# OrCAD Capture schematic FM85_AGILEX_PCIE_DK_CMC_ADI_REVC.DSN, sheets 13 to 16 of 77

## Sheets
13 FPGA BANK 2E: size B
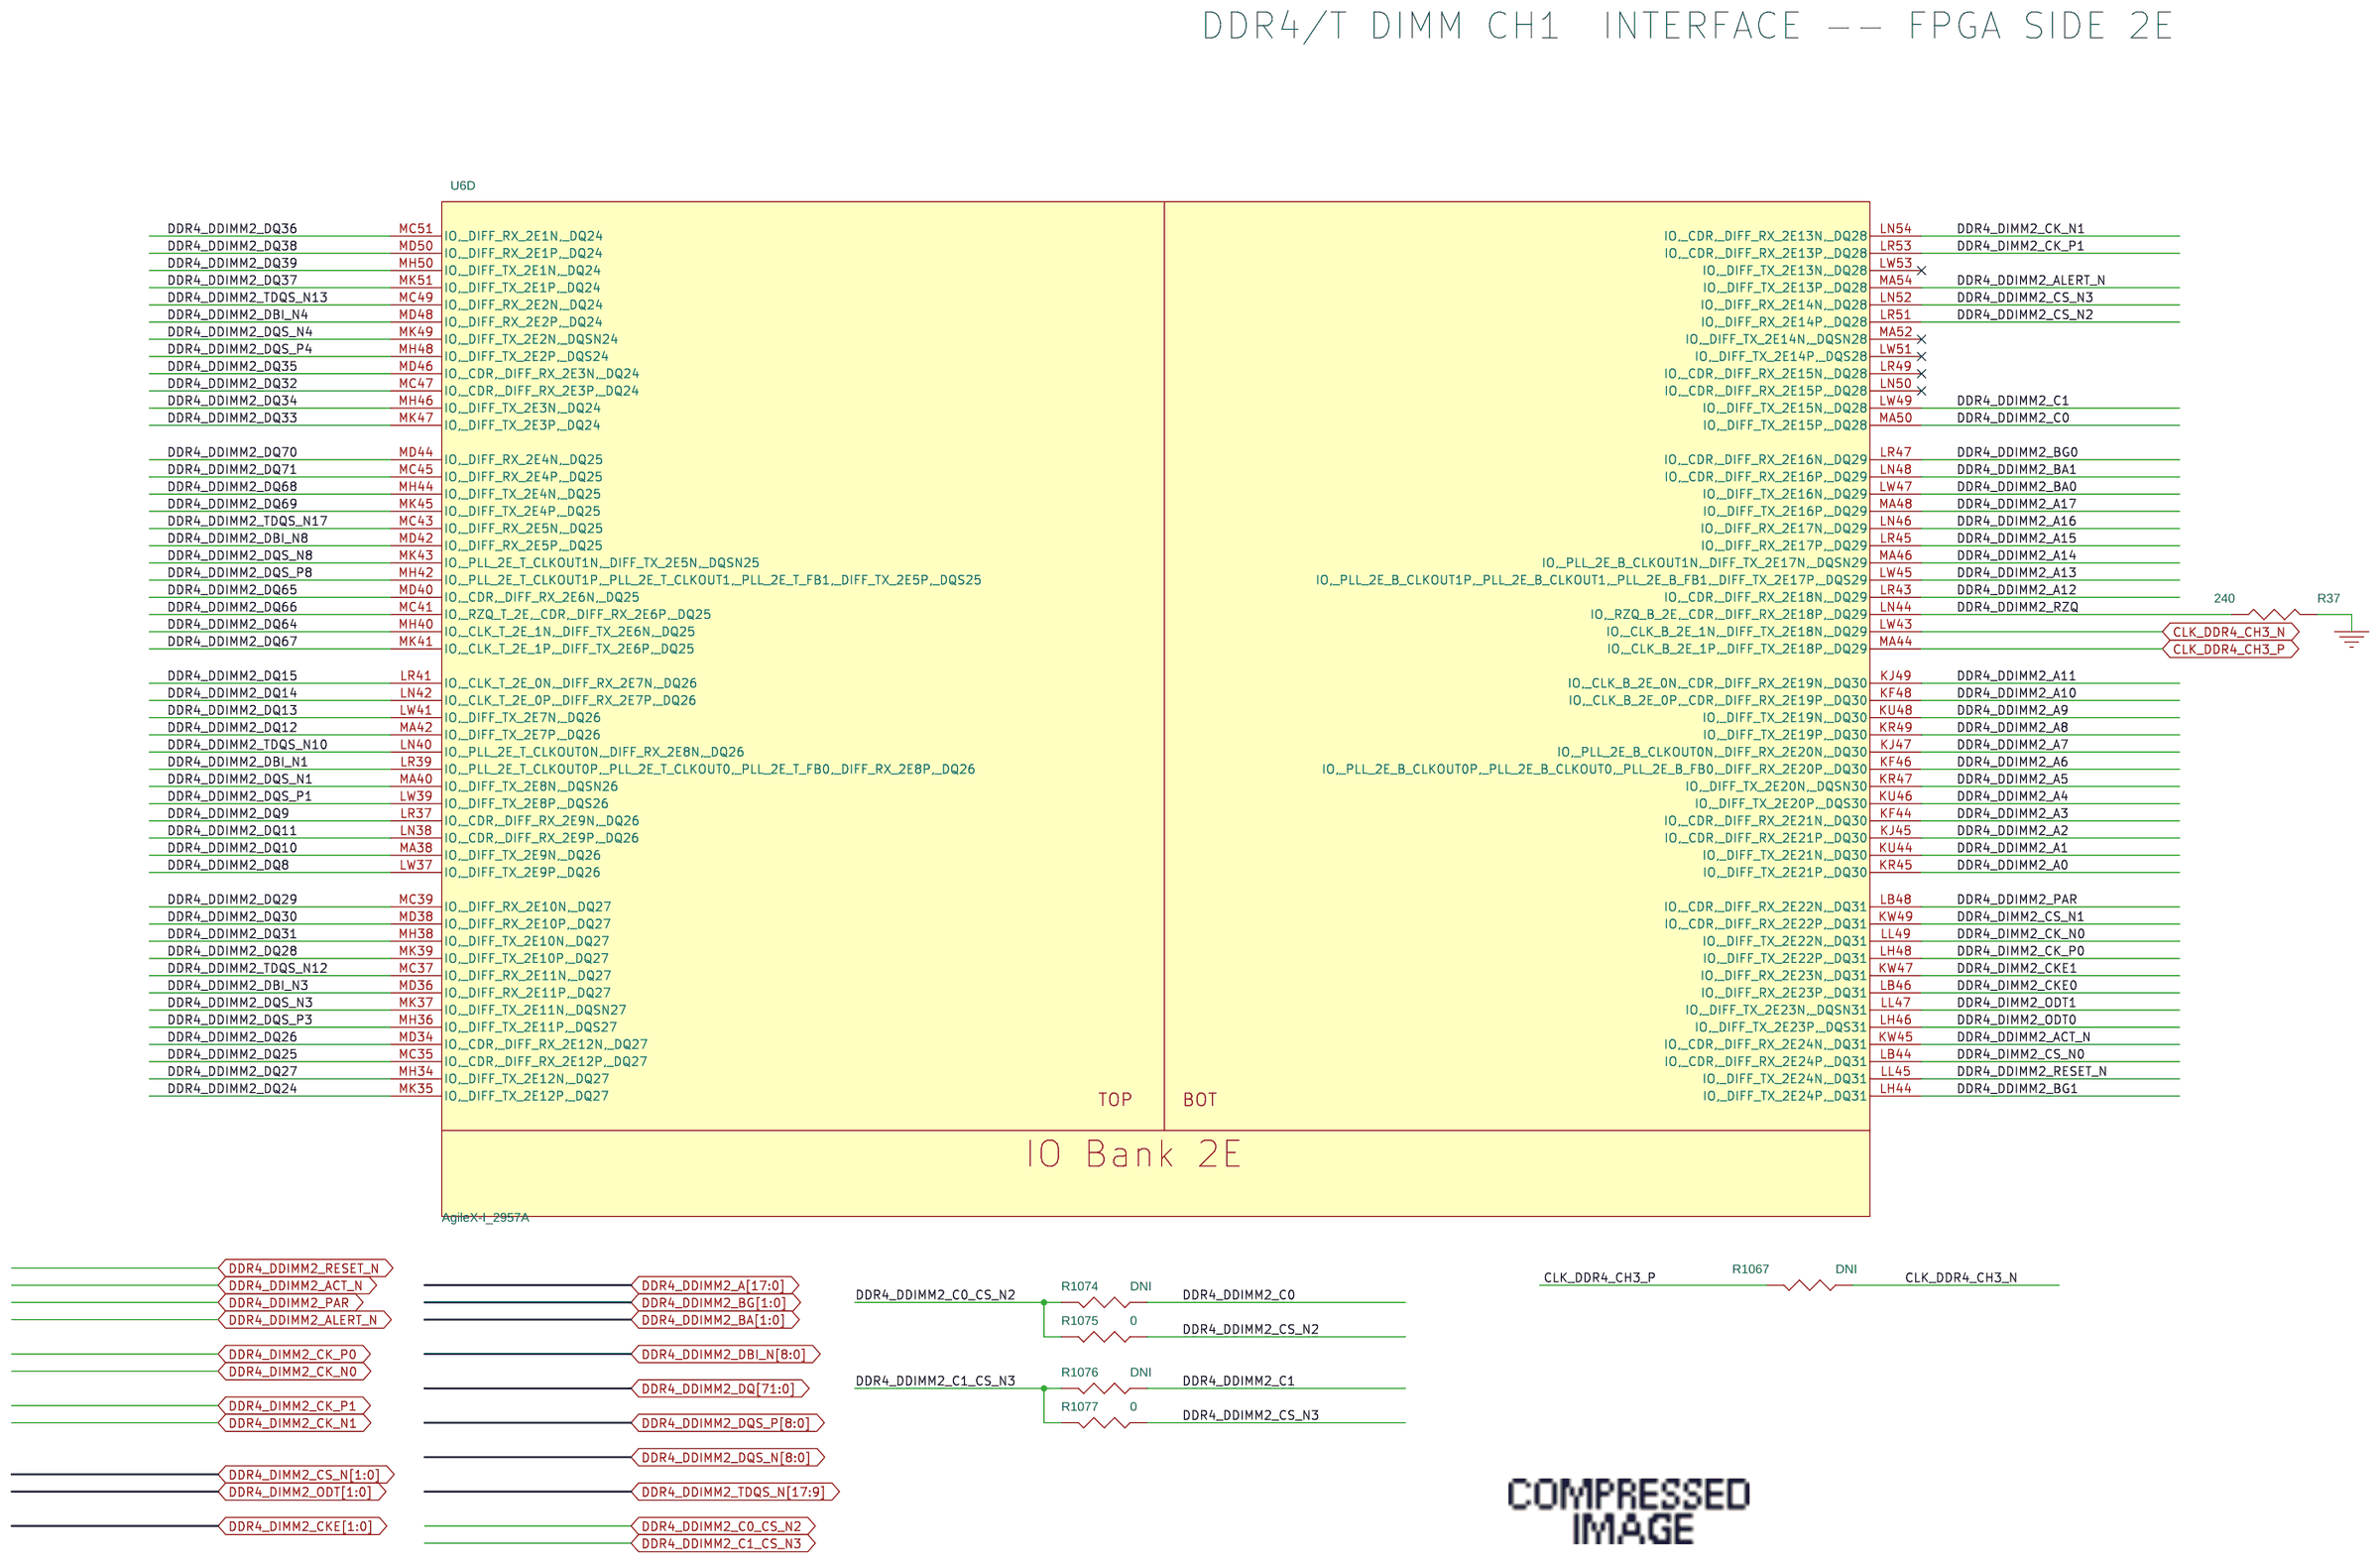
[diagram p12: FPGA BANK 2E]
14 DDR4 CH1 Component 1: size B
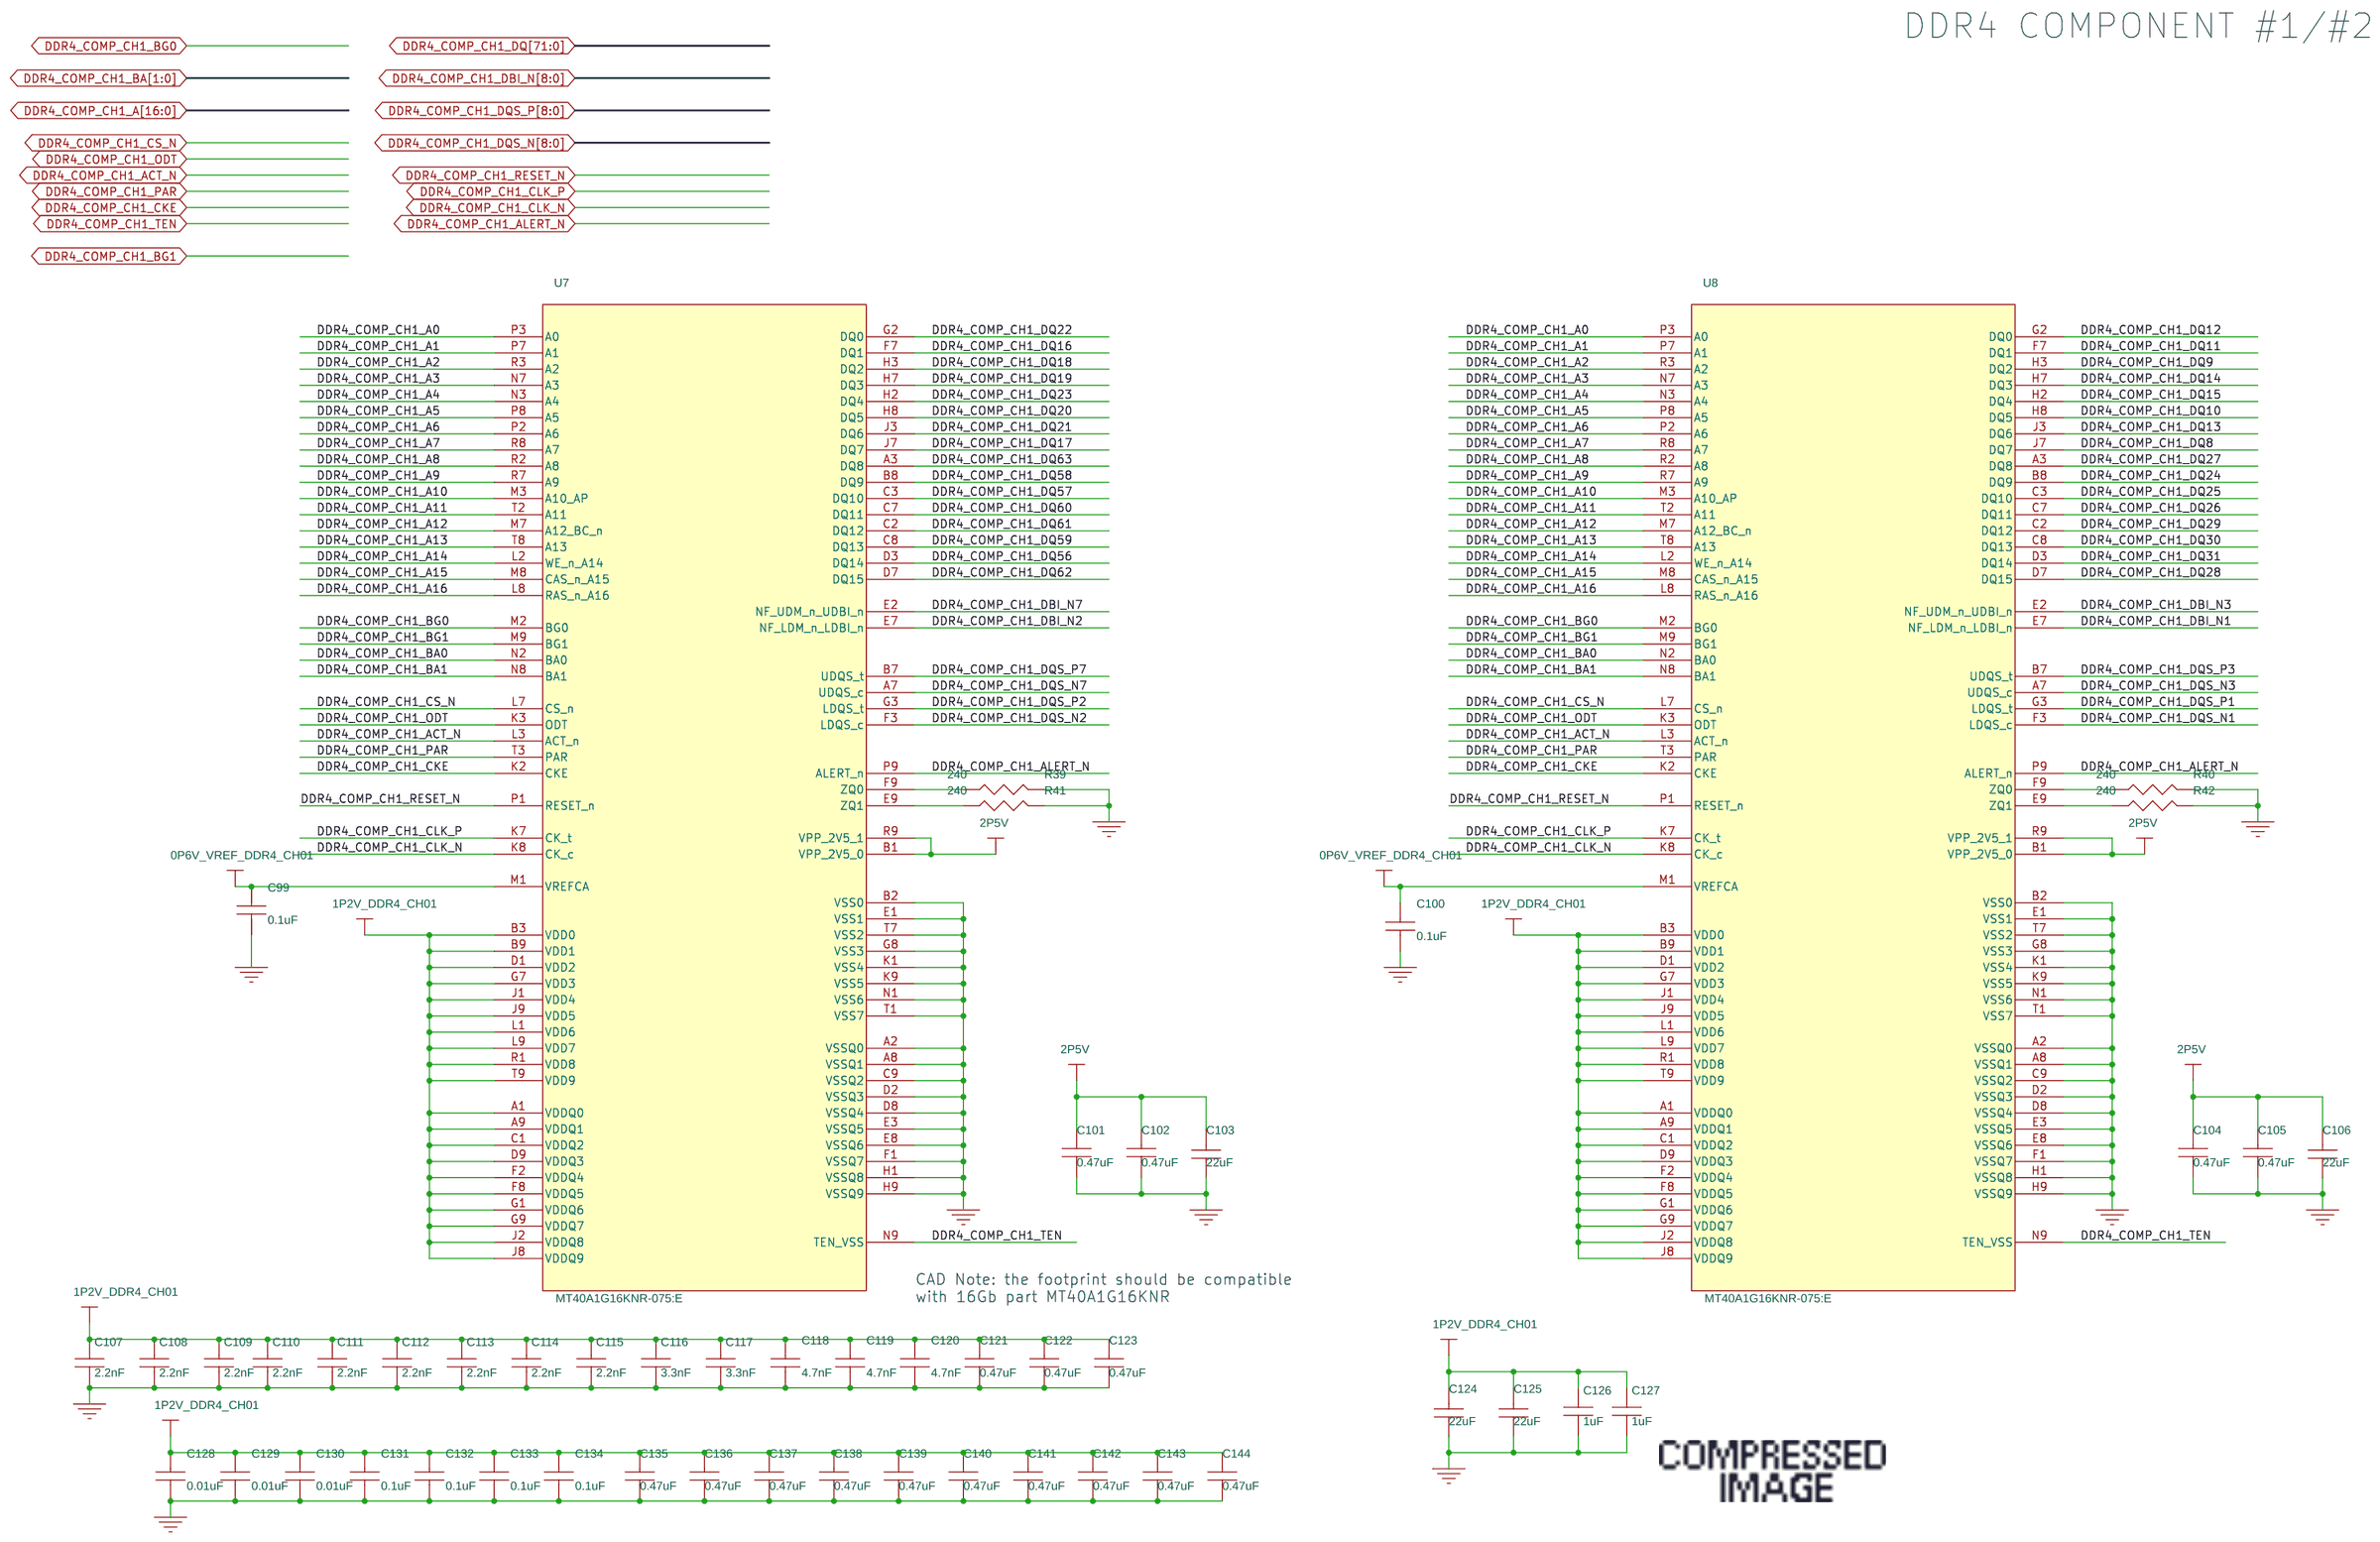
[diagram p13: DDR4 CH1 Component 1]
15 DDR4 CH1 Component 2: size B
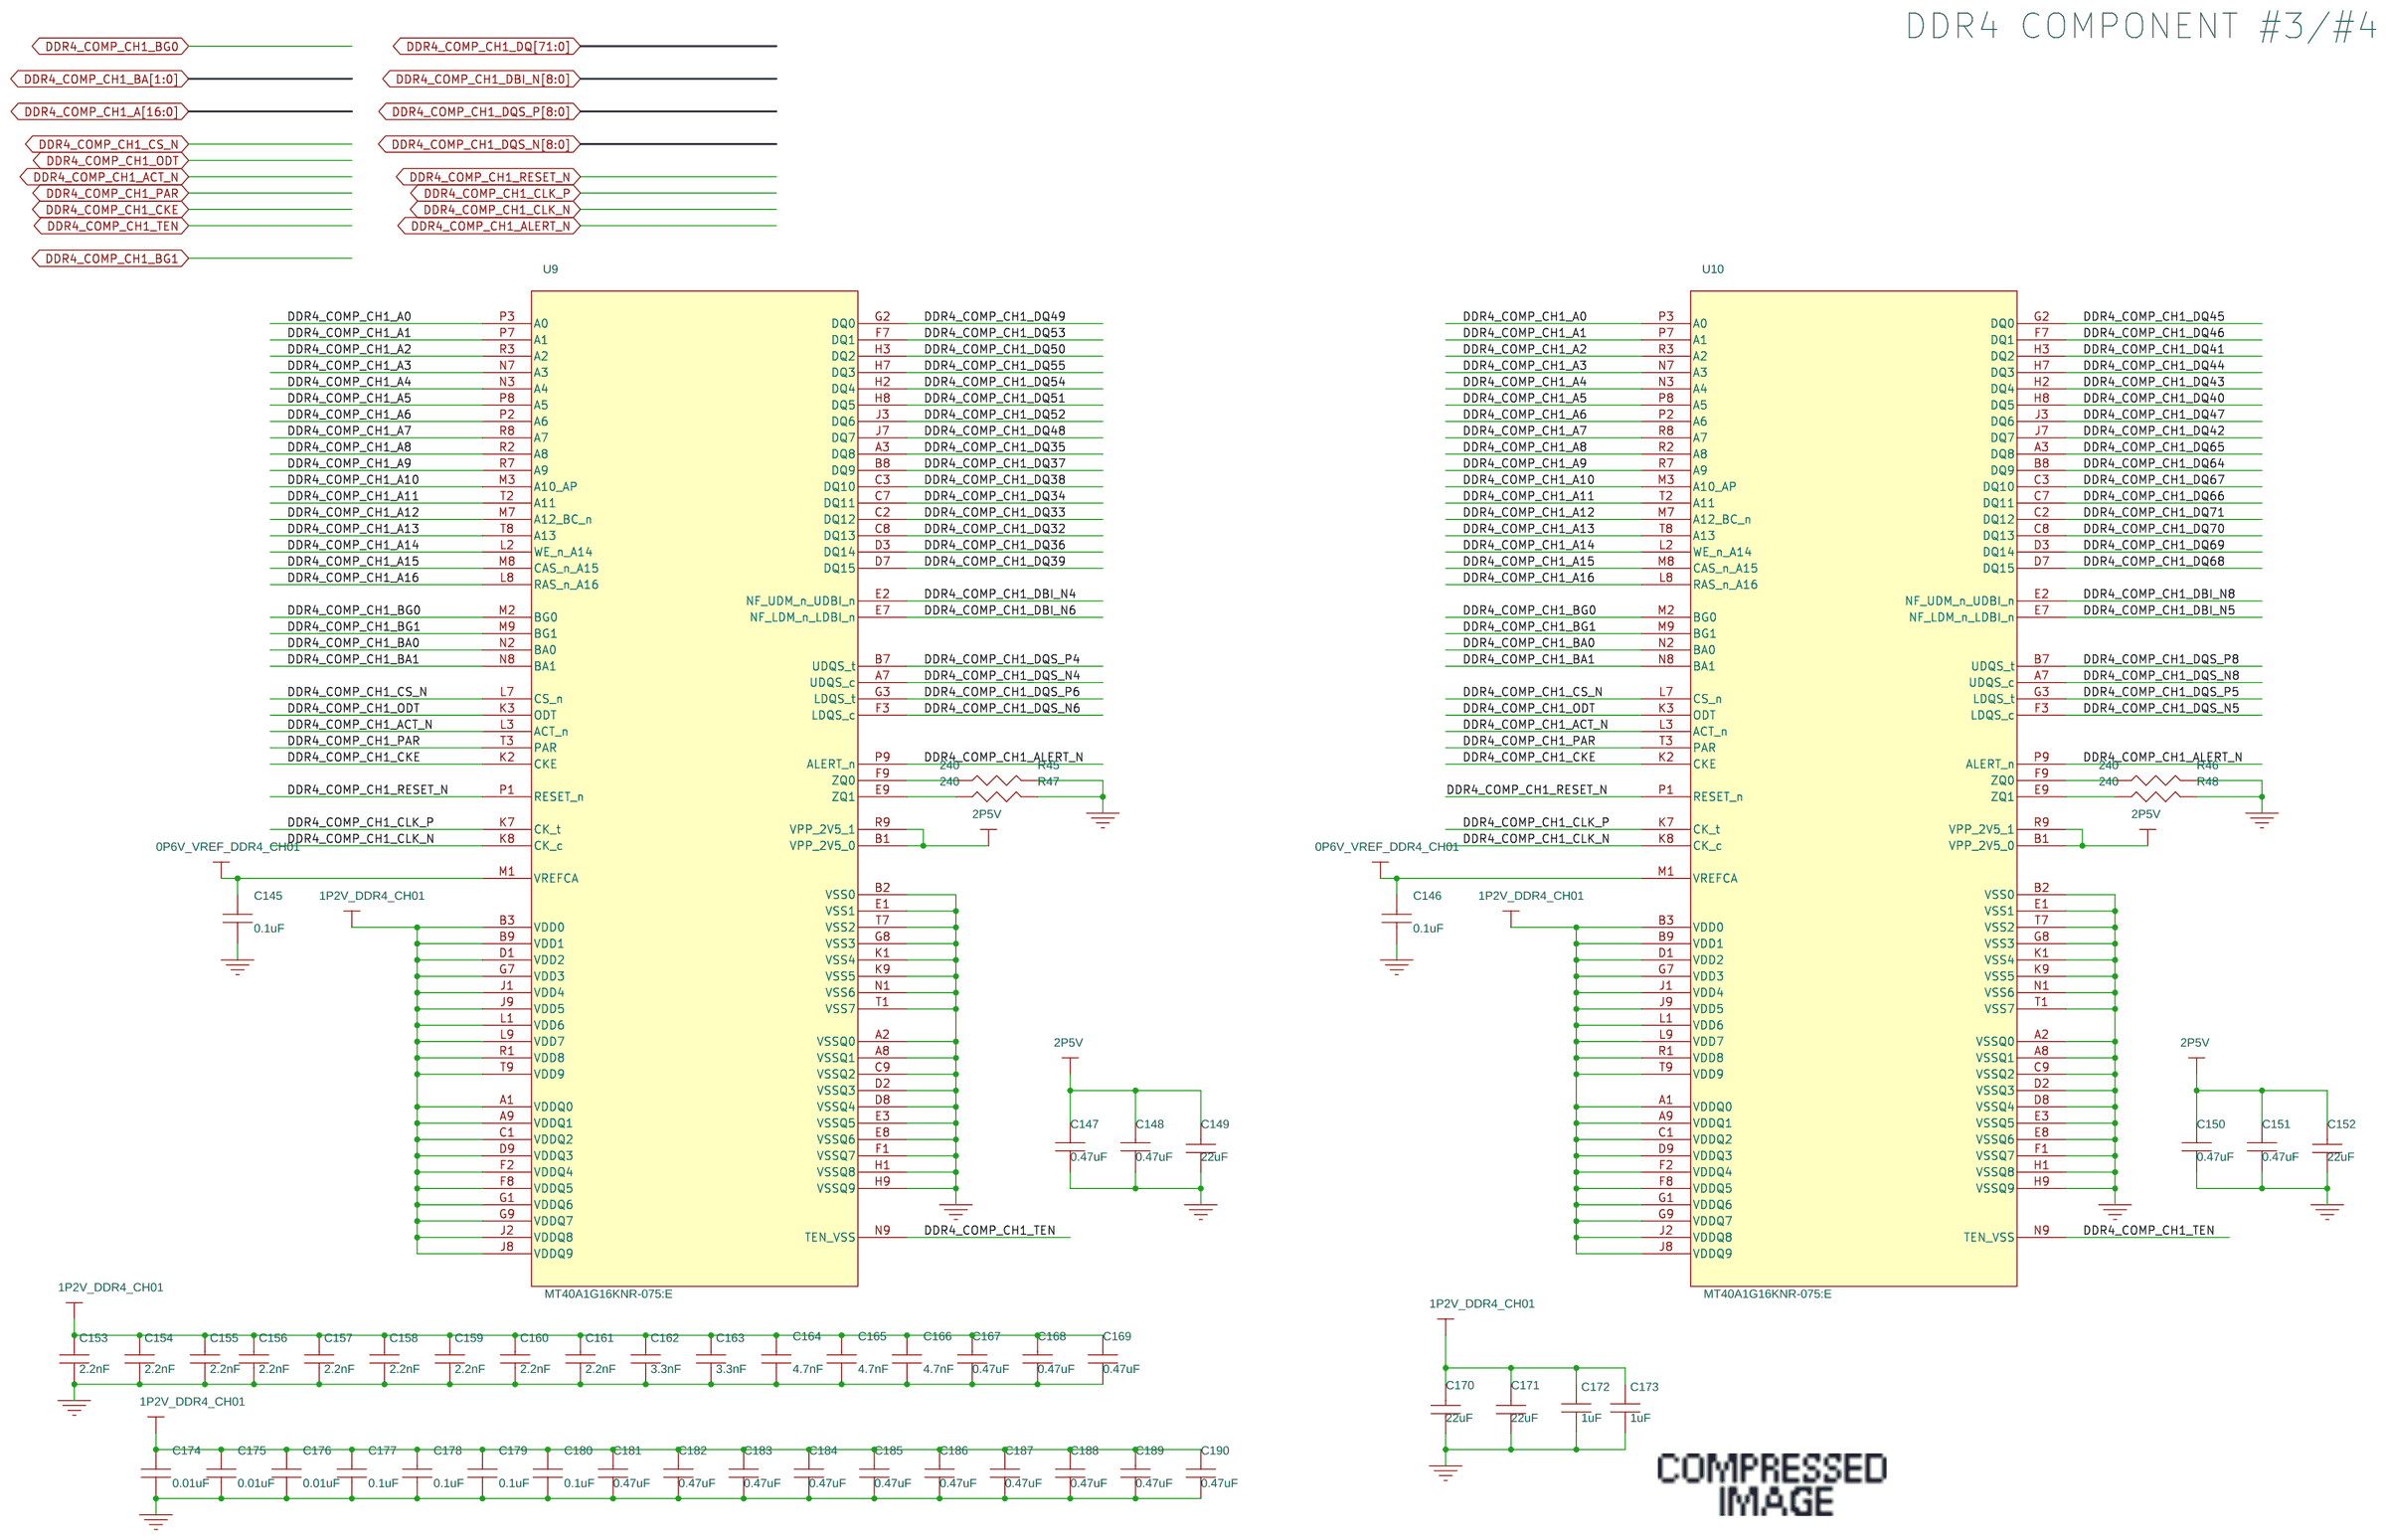
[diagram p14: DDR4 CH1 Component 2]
16 DDR4 CH1 Comp Termination: size B
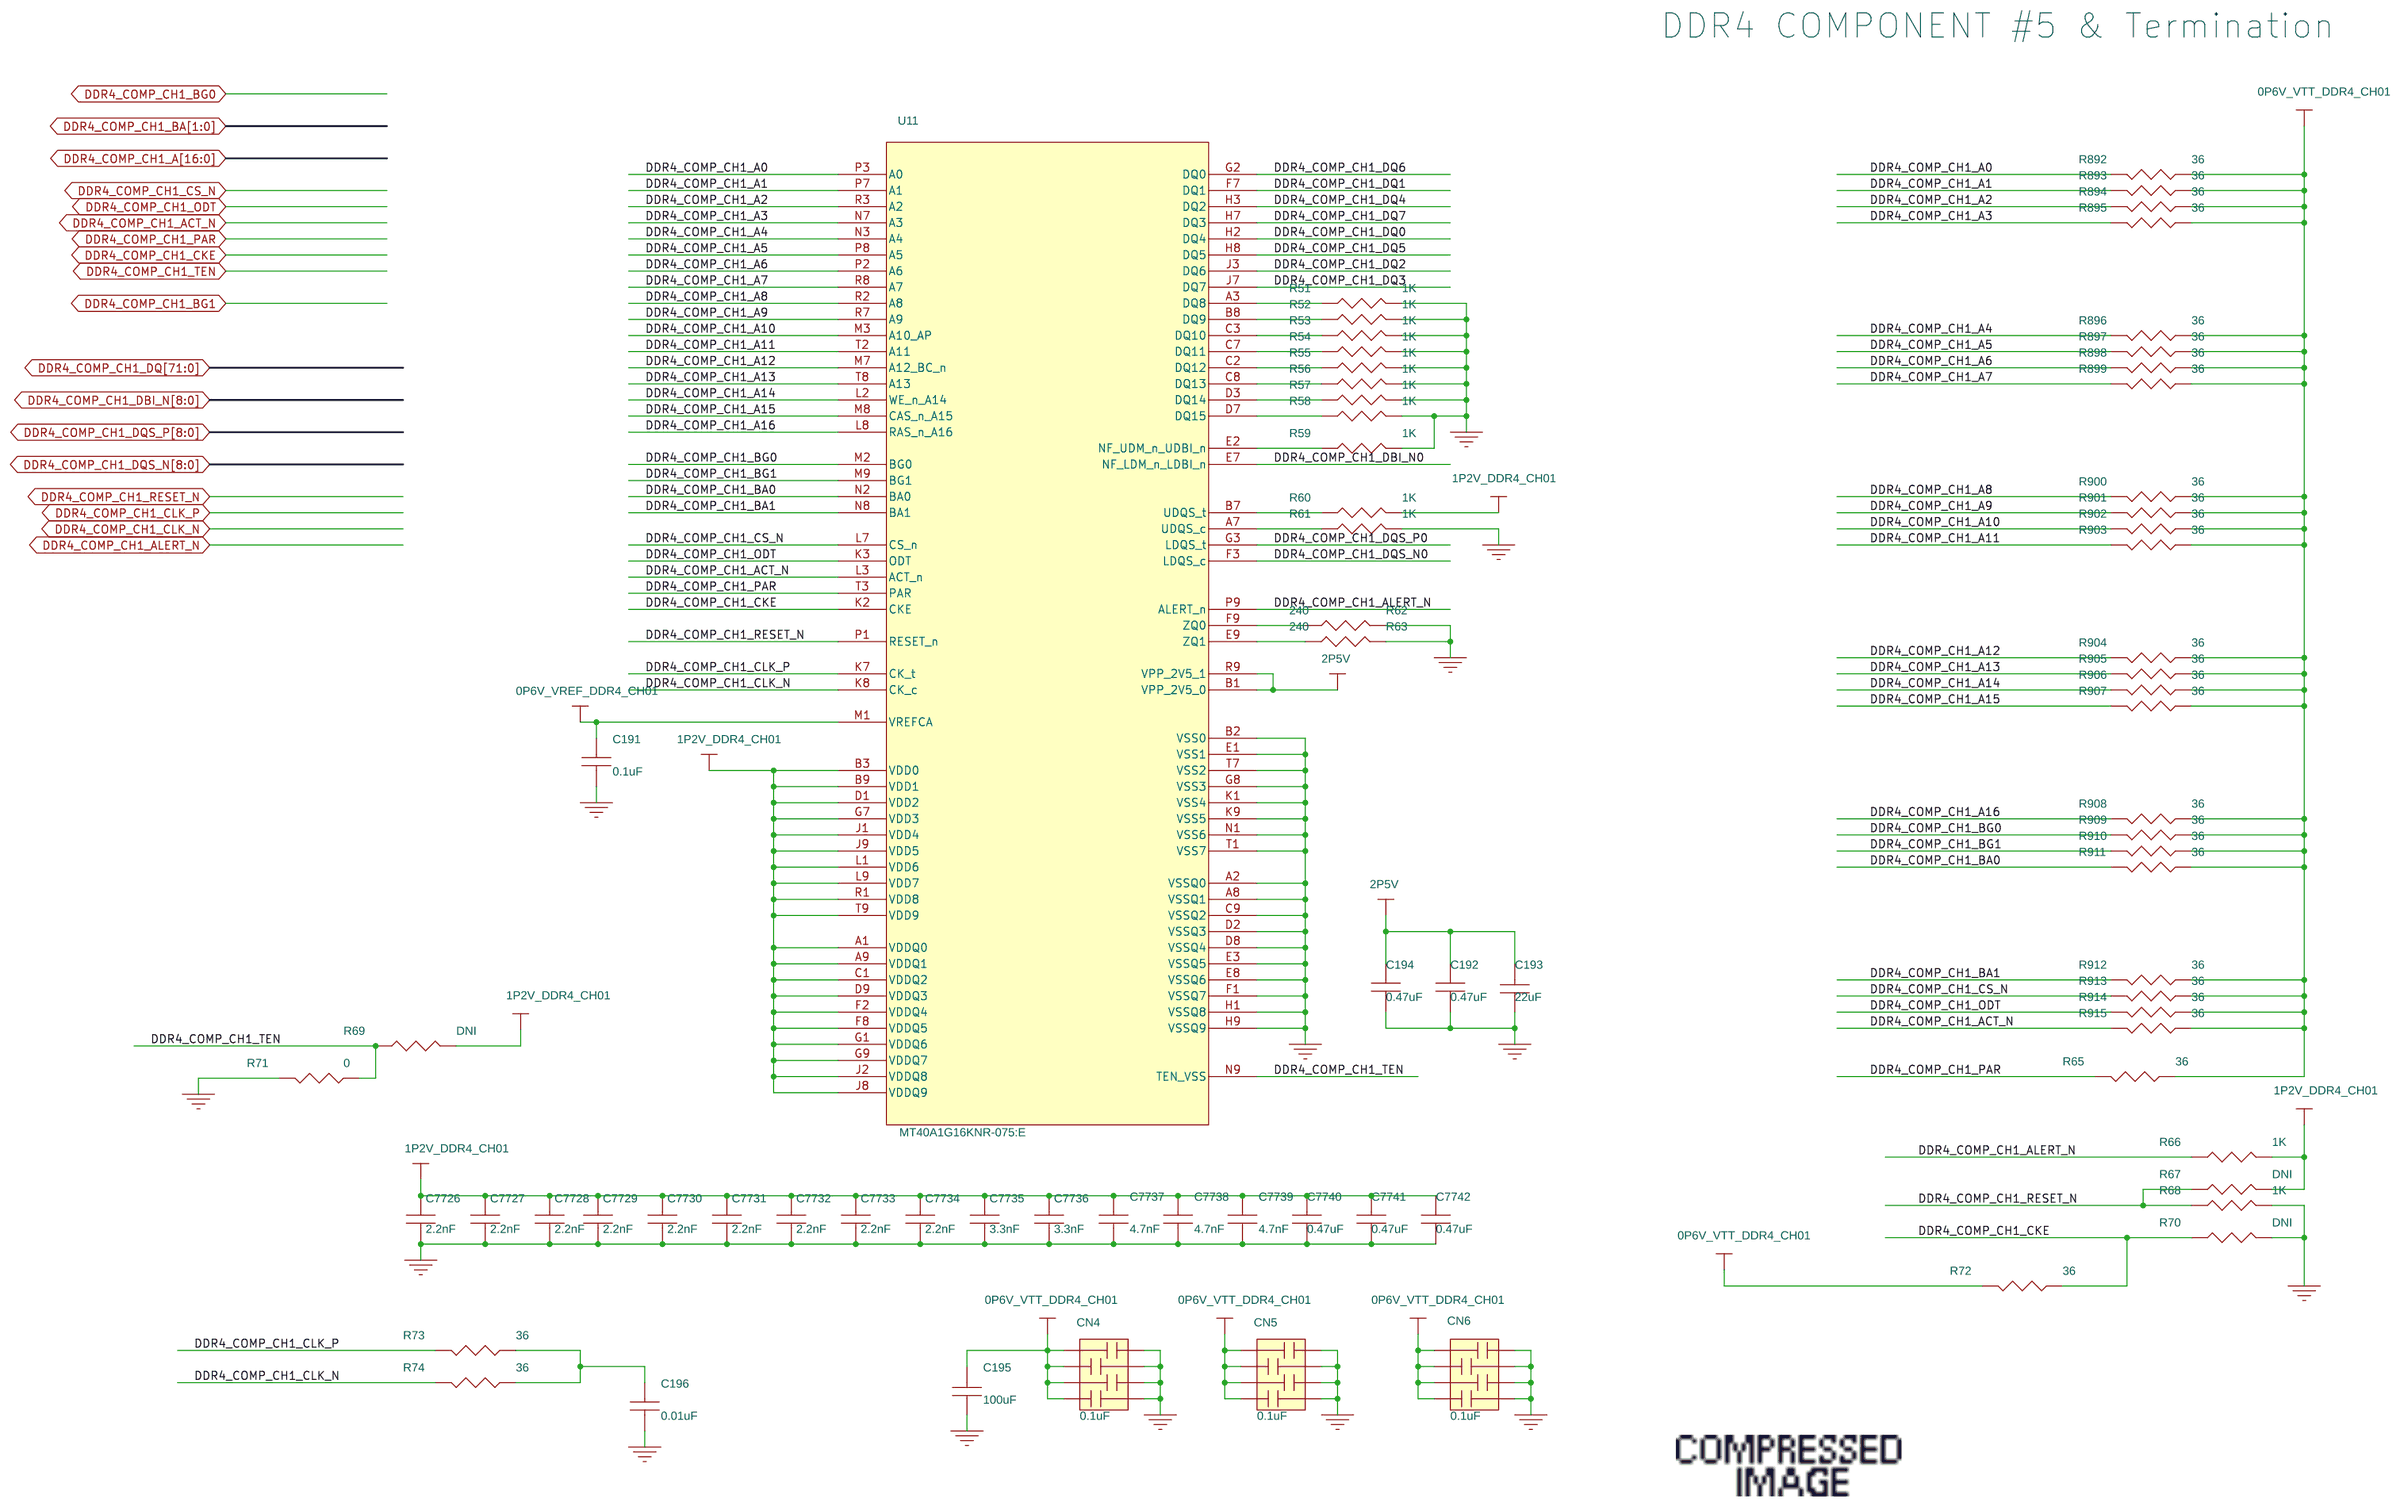
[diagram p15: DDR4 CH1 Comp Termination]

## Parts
sheet DDR4 CH1 Comp Termination
C191  0.1uF  [0402]
C192  0.47uF  [0402]
C193  22uF  [0603]
C194  0.47uF  [0402]
C195  100uF  [1206]
C196  0.01uF  [0402]
C7726  2.2nF  [0402]
C7727  2.2nF  [0402]
C7728  2.2nF  [0402]
C7729  2.2nF  [0402]
C7730  2.2nF  [0402]
C7731  2.2nF  [0402]
C7732  2.2nF  [0402]
C7733  2.2nF  [0402]
C7734  2.2nF  [0402]
C7735  3.3nF  [0402]
C7736  3.3nF  [0402]
C7737  4.7nF  [0402]
C7738  4.7nF  [0402]
C7739  4.7nF  [0402]
C7740  0.47uF  [0402]
C7741  0.47uF  [0402]
C7742  0.47uF  [0402]
CN4  0.1uF  [CAP_PACK_4_1206]
CN5  0.1uF  [CAP_PACK_4_1206]
CN6  0.1uF  [CAP_PACK_4_1206]
R51  1K  [0402]
R52  1K  [0402]
R53  1K  [0402]
R54  1K  [0402]
R55  1K  [0402]
R56  1K  [0402]
R57  1K  [0402]
R58  1K  [0402]
R59  1K  [0402]
R60  1K  [0402]
R61  1K  [0402]
R62  240  [0402]
R63  240  [0402]
R65  36  [0402]
R66  1K  [0402]
R67  DNI  [0402]
R68  1K  [0402]
R69  DNI  [0402]
R70  DNI  [0402]
R71  0  [0402]
R72  36  [0402]
R73  36  [0402]
R74  36  [0402]
R892  36  [0402]
R893  36  [0402]
R894  36  [0402]
R895  36  [0402]
R896  36  [0402]
R897  36  [0402]
R898  36  [0402]
R899  36  [0402]
R900  36  [0402]
R901  36  [0402]
R902  36  [0402]
R903  36  [0402]
R904  36  [0402]
R905  36  [0402]
R906  36  [0402]
R907  36  [0402]
R908  36  [0402]
R909  36  [0402]
R910  36  [0402]
R911  36  [0402]
R912  36  [0402]
R913  36  [0402]
R914  36  [0402]
R915  36  [0402]
U11  MT40A1G16KNR-075:E  [FBGA96]
sheet DDR4 CH1 Component 1
C99  0.1uF  [0402]
C100  0.1uF  [0402]
C101  0.47uF  [0402]
C102  0.47uF  [0402]
C103  22uF  [0603]
C104  0.47uF  [0402]
C105  0.47uF  [0402]
C106  22uF  [0603]
C107  2.2nF  [0402]
C108  2.2nF  [0402]
C109  2.2nF  [0402]
C110  2.2nF  [0402]
C111  2.2nF  [0402]
C112  2.2nF  [0402]
C113  2.2nF  [0402]
C114  2.2nF  [0402]
C115  2.2nF  [0402]
C116  3.3nF  [0402]
C117  3.3nF  [0402]
C118  4.7nF  [0402]
C119  4.7nF  [0402]
C120  4.7nF  [0402]
C121  0.47uF  [0402]
C122  0.47uF  [0402]
C123  0.47uF  [0402]
C124  22uF  [0603]
C125  22uF  [0603]
C126  1uF  [0402]
C127  1uF  [0402]
C128  0.01uF  [0402]
C129  0.01uF  [0402]
C130  0.01uF  [0402]
C131  0.1uF  [0402]
C132  0.1uF  [0402]
C133  0.1uF  [0402]
C134  0.1uF  [0402]
C135  0.47uF  [0402]
C136  0.47uF  [0402]
C137  0.47uF  [0402]
C138  0.47uF  [0402]
C139  0.47uF  [0402]
C140  0.47uF  [0402]
C141  0.47uF  [0402]
C142  0.47uF  [0402]
C143  0.47uF  [0402]
C144  0.47uF  [0402]
R39  240  [0402]
R40  240  [0402]
R41  240  [0402]
R42  240  [0402]
U7  MT40A1G16KNR-075:E  [FBGA96]
U8  MT40A1G16KNR-075:E  [FBGA96]
sheet DDR4 CH1 Component 2
C145  0.1uF  [0402]
C146  0.1uF  [0402]
C147  0.47uF  [0402]
C148  0.47uF  [0402]
C149  22uF  [0603]
C150  0.47uF  [0402]
C151  0.47uF  [0402]
C152  22uF  [0603]
C153  2.2nF  [0402]
C154  2.2nF  [0402]
C155  2.2nF  [0402]
C156  2.2nF  [0402]
C157  2.2nF  [0402]
C158  2.2nF  [0402]
C159  2.2nF  [0402]
C160  2.2nF  [0402]
C161  2.2nF  [0402]
C162  3.3nF  [0402]
C163  3.3nF  [0402]
C164  4.7nF  [0402]
C165  4.7nF  [0402]
C166  4.7nF  [0402]
C167  0.47uF  [0402]
C168  0.47uF  [0402]
C169  0.47uF  [0402]
C170  22uF  [0603]
C171  22uF  [0603]
C172  1uF  [0402]
C173  1uF  [0402]
C174  0.01uF  [0402]
C175  0.01uF  [0402]
C176  0.01uF  [0402]
C177  0.1uF  [0402]
C178  0.1uF  [0402]
C179  0.1uF  [0402]
C180  0.1uF  [0402]
C181  0.47uF  [0402]
C182  0.47uF  [0402]
C183  0.47uF  [0402]
C184  0.47uF  [0402]
C185  0.47uF  [0402]
C186  0.47uF  [0402]
C187  0.47uF  [0402]
C188  0.47uF  [0402]
C189  0.47uF  [0402]
C190  0.47uF  [0402]
R45  240  [0402]
R46  240  [0402]
R47  240  [0402]
R48  240  [0402]
U9  MT40A1G16KNR-075:E  [FBGA96]
U10  MT40A1G16KNR-075:E  [FBGA96]
sheet FPGA BANK 2E
R37  240  [0402]
R1067  DNI  [0402]
R1074  DNI  [0402]
R1075  0  [0402]
R1076  DNI  [0402]
R1077  0  [0402]
sheet FPGA BANK 2F
U6  AgileX-I_2957A  [fbga2957a_hex_p56x45]  (sections A,B,C,D,E,F,G,H,I,J,K,L,M,N,O,P,Q,R,S,T,U,V,W,X,Y,Z)

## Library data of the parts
C99 C100 C131-C134 C145 C146 C177 C178 C180 C191 = CAP: CAPC,  X7R, 0402, 0.1uF, 25V, ±20%; Item Num: K13660-001; LIFECYCLE_PHASE: Active; Lead Free Status: Lead Free; MFR_LIFECYCLE: Active; Manufacturer: Murata; Manufacturer Part Num: GRM155R71E104KE14D; Num Pins: 2; PART_SUBCLASS: CAPACITORS; Part Class: CAPACITORS; RATED_VOLTAGE: 25V; RoHS Compliant: RoHS Compliant; Tolerance: +80%/-20%
C101 C102 C104 C105 C121-C123 C135-C144 C147 C148 C150 C151 C167-C169 C181-C190 C192 C194 C7740-C7742 = CAP: CAP - CER, .47UF, 10V, X5R, 0402; AGILE_LINK: http://sj-agile9app/Agile/PLMServlet?action=OpenEmailObject&classid=10000&objid=256989651; Item Num: H75789-001; LIFECYCLE_PHASE: Active; Lead Free Status: Lead Free; MFR_LIFECYCLE: Active; Manufacturer: Murata; Manufacturer Part Num: GRM155R61A474KE15D; Num Pins: 2; PART_SUBCLASS: CAPACITORS; Part Class: CAPACITORS; RATED_VOLTAGE: 10V; RoHS Compliant: RoHS Compliant; Tolerance: +80%/-20%
C103 C106 C124 C125 C149 C152 C170 C171 C193 = CAP: CAP CER 22UF 6.3V X6S 0603; AGILE_LINK: http://sj-agile9app/Agile/PLMServlet?action=OpenEmailObject&classid=10000&objid=257560276; Item Num: H63299-001; LIFECYCLE_PHASE: Active; Lead Free Status: Not Lead Free; MFR_LIFECYCLE: Active; Manufacturer: Murata; Manufacturer Part Num: GRM188C80J226ME15D; Num Pins: 2; PART_SUBCLASS: CAPACITORS; RATED_VOLTAGE: 6.3V; RoHS Compliant: RoHS Compliant; TOLERANCE: 20%; Temperature Coefficient: X6S
C195 = CAP: CAP CER 100UF 6.3V X6T 1206; AGILE_LINK: http://sj-agile9app/Agile/PLMServlet?action=OpenEmailObject&classid=10000&objid=257560276; Item Num: H65271-004; LIFECYCLE_PHASE: Active; Lead Free Status: Lead Free; MFR_LIFECYCLE: Active; Manufacturer: Murata; Manufacturer Part Num: GRM31CD80J107ME39L; Num Pins: 2; PART_SUBCLASS: CAPACITORS; RATED_VOLTAGE: 6.3V; RoHS Compliant: RoHS Compliant; TOLERANCE: 20%; Temperature Coefficient: X6T
C128-C130 C174-C176 C196 = CAP: CAP, CER .01UF 16V X7R 0402; Item Num: A36096-007; Lead Free Status: No; Manufacturer: Murata; Manufacturer Part Num: GRM155R71C103KA01D; Manufacturer's Part No.: GRM155R71C103KA01D; Num Pins: 2; Part Class: CAPACITORS; Price: 0; RoHS Compliant: Yes
C7726-C7734 = CAP: CAP CER 2200PF 50V 10% X7R 0402; AGILE_LINK: http://sj-agile9app/Agile/PLMServlet?action=OpenEmailObject&classid=10000&objid=204246494; CAPACITANCE: 2200pF; Item Num: H63810-001; LIFECYCLE_PHASE: Active; Manufacturer: Murata; Manufacturer Part Num: GRM155R71H222KA01D; Num Pins: 2; PART_SUBCLASS: CAPACITORS; RATED_VOLTAGE: 50V; TOLERANCE: +/-10%
C116 C117 C162 C163 C7735 C7736 = CAP: CAP, CERAMIC, 3300PF, 10%, 50V, X7R, 0402; AGILE_LINK: http://sj-agile9app/Agile/PLMServlet?action=OpenEmailObject&classid=10000&objid=257002141; Item Num: K13754-001; LIFECYCLE_PHASE: Active; Lead Free Status: Lead Free; MFR_LIFECYCLE: Active; Manufacturer: Murata; Manufacturer Part Num: GRM155F51H332ZA01x; Num Pins: 2; PART_SUBCLASS: CAPACITORS; RATED_VOLTAGE: 50V; RoHS Compliant: RoHS Compliant; TOLERANCE: +/-10%
C118-C120 C164-C166 C7737-C7739 = CAP: CAP - CER 4700PF 50V 10% X7R 0402; AGILE_LINK: http://sj-agile9app/Agile/PLMServlet?action=OpenEmailObject&classid=10000&objid=215384813; Item Num: G24897-001; LIFECYCLE_PHASE: Active; Lead Free Status: Lead Free; MFR_LIFECYCLE: Active; Manufacturer: Murata; Manufacturer Part Num: GRM155R71H472KA01D; Num Pins: 2; PACKAGING: Tape & Reel (TR); PART_SUBCLASS: CAPACITORS; RATED_VOLTAGE: 50V; RoHS Compliant: RoHS Compliant; Supplier Part Num: GRM155R71H472KA01D; Tolerance: +/-10%
CN4-CN6 = CAP_ARRAY: CAPNET, 4 CAPS, CERAMIC, 0.1uF, 1206, 20%, 16VDC, X7R; Item Num: J41786-001; Manufacturer: Panasonic; Manufacturer Part Num: ECJ-RVB1C104M
R51-R61 R66-R70 = RESISTOR: RES,1.00K OHMS,1.0%,1/16W,0402; Item Num: G60609-021; Lead Free Status: No; Manufacturer: Panasonic; Manufacturer Part Num: ERJ-2RKF1001X; Num Pins: 2; Part Class: Resistors
R37 R39-R42 R45-R48 R62 R63 = RESISTOR: RES - 240 OHM, 1/16W, 1%, 0402 SMD; Item Num: K15783-001; LIFECYCLE_PHASE: Active; Lead Free Status: Lead Free; MFR_LIFECYCLE: Active; Manufacturer: Panasonic; Manufacturer Part Num: ERJ-2RKF2400X; Num Pins: 2; PART_SUBCLASS: RESISTORS; RoHS Compliant: RoHS Compliant
R65 R72-R74 R892-R915 = RESISTOR: RES_D,0402,36.00OHM,1.00%,1/16W,; Item Num: A93548-623; Lead Free Status: Yes; Manufacturer: VISHAY; Manufacturer Part Num: CRCW040236R0FKED; Num Pins: 2; Part Class: Resistors; Price: 0
R71 R1074-R1077 = RES_0_OHM_5%_1_16W_0402_SMD: Item Num: H30887-001
U7-U11 = MT40A1G16HBA-083E_0: IC - Memory, 64M x 16 x 16 Banks x 1 Rank, 1.2V DDR4 SDRAM, TwinDie; Item Num: K20740-001; Manufacturer: Micron
C107-C115 C153-C161 = CAP: CAP CER 2200PF 50V 10% X7R 0402; AGILE_LINK: http://sj-agile9app/Agile/PLMServlet?action=OpenEmailObject&classid=10000&objid=204246494; CAPACITANCE: 2200pF; Item Num: A36096-022; LIFECYCLE_PHASE: Active; Manufacturer: Murata; Manufacturer Part Num: GRM155R71H222KA01D; Num Pins: 2; PART_SUBCLASS: CAPACITORS; RATED_VOLTAGE: 50V; TOLERANCE: +/-10%
C126 C127 C172 C173 = CAP: CAP - CER, 1uF, 10V, +/-10%, X5R, 0402; Item Num: G61001-001; Lead Free Status: Yes; Manufacturer: Murata; Manufacturer Part Num: GRM155R61A105KE15D; Num Pins: 2; Part Class: CAPACITORS; RoHS Compliant: Yes
C179 = CAP: CAPC,  X7R, 0402, 0.1uF, 25V, ±20%; Dielectric: Y5V; Item Num: K13660-001; LIFECYCLE_PHASE: Active; Lead Free Status: Lead Free; MFR_LIFECYCLE: Active; Manufacturer: Murata; Manufacturer Part Num: GRM155R71E104KE14D; Num Pins: 2; PART_SUBCLASS: CAPACITORS; Part Class: CAPACITORS; RATED_VOLTAGE: 25V; RoHS Compliant: RoHS Compliant; Tolerance: +80%/-20%
R1067 = RESISTOR: RES,100 OHMS,1.0%,1/16W,0402; Item Num: A36092-043; Lead Free Status: No; Manufacturer: Panasonic; Manufacturer Part Num: ERJ-2RKF1000X; Manufacturer's Part No.: ERJ-2RKF1000X; Num Pins: 2; Part Class: RESISTORS; Price: 0; RoHS Compliant: Yes
U6 = AgileX-I_2957A: Item Num: 99C7VA

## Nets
GND: C99.2 C100.2 C101.2 C102.2 C103.1 C104.2 C105.2 C106.1 C107.2 C108.2 C109.2 C110.2 C111.2 C112.2 C113.2 C114.2 C115.2 C116.2 C117.2 C118.2 C119.2 C120.2 C121.2 C122.2 C123.2 C124.1 C125.1 C126.2 C127.2 C128.2 C129.2 C130.2 C131.2 C132.2 C133.2 C134.2 C135.2 C136.2 C137.2 C138.2 C139.2 C140.2 C141.2 C142.2 C143.2 C144.2 C145.2 C146.2 C147.2 C148.2 C149.1 C150.2 C151.2 C152.1 C153.2 C154.2 C155.2 C156.2 C157.2 C158.2 C159.2 C160.2 C161.2 C162.2 C163.2 C164.2 C165.2 C166.2 C167.2 C168.2 C169.2 C170.1 C171.1 C172.2 C173.2 C174.2 C175.2 C176.2 C177.2 C178.2 C179.2 C180.2 C181.2 C182.2 C183.2 C184.2 C185.2 C186.2 C187.2 C188.2 C189.2 C190.2 C191.2 C192.2 C193.1 C194.2 C195.1 C196.2 C7726.2 C7727.2 C7728.2 C7729.2 C7730.2 C7731.2 C7732.2 C7733.2 C7734.2 C7735.2 C7736.2 C7737.2 C7738.2 C7739.2 C7740.2 C7741.2 C7742.2 CN4.5 CN4.6 CN4.7 CN4.8 CN5.5 CN5.6 CN5.7 CN5.8 CN6.5 CN6.6 CN6.7 CN6.8 R37.2 R39.2 R40.2 R41.2 R42.2 R45.2 R46.2 R47.2 R48.2 R51.1 R52.1 R53.1 R54.1 R55.1 R56.1 R57.1 R58.1 R59.1 R61.1 R62.2 R63.2 R68.1 R70.1 R71.2 U7.A2(VSSQ0) U7.A8(VSSQ1) U7.B2(VSS0) U7.C9(VSSQ2) U7.D2(VSSQ3) U7.D8(VSSQ4) U7.E1(VSS1) U7.E3(VSSQ5) U7.E8(VSSQ6) U7.F1(VSSQ7) U7.G8(VSS3) U7.H1(VSSQ8) U7.H9(VSSQ9) U7.K1(VSS4) U7.K9(VSS5) U7.N1(VSS6) U7.T1(VSS7) U7.T7(VSS2) U8.A2(VSSQ0) U8.A8(VSSQ1) U8.B2(VSS0) U8.C9(VSSQ2) U8.D2(VSSQ3) U8.D8(VSSQ4) U8.E1(VSS1) U8.E3(VSSQ5) U8.E8(VSSQ6) U8.F1(VSSQ7) U8.G8(VSS3) U8.H1(VSSQ8) U8.H9(VSSQ9) U8.K1(VSS4) U8.K9(VSS5) U8.N1(VSS6) U8.T1(VSS7) U8.T7(VSS2) U9.A2(VSSQ0) U9.A8(VSSQ1) U9.B2(VSS0) U9.C9(VSSQ2) U9.D2(VSSQ3) U9.D8(VSSQ4) U9.E1(VSS1) U9.E3(VSSQ5) U9.E8(VSSQ6) U9.F1(VSSQ7) U9.G8(VSS3) U9.H1(VSSQ8) U9.H9(VSSQ9) U9.K1(VSS4) U9.K9(VSS5) U9.N1(VSS6) U9.T1(VSS7) U9.T7(VSS2) U10.A2(VSSQ0) U10.A8(VSSQ1) U10.B2(VSS0) U10.C9(VSSQ2) U10.D2(VSSQ3) U10.D8(VSSQ4) U10.E1(VSS1) U10.E3(VSSQ5) U10.E8(VSSQ6) U10.F1(VSSQ7) U10.G8(VSS3) U10.H1(VSSQ8) U10.H9(VSSQ9) U10.K1(VSS4) U10.K9(VSS5) U10.N1(VSS6) U10.T1(VSS7) U10.T7(VSS2) U11.A2(VSSQ0) U11.A8(VSSQ1) U11.B2(VSS0) U11.C9(VSSQ2) U11.D2(VSSQ3) U11.D8(VSSQ4) U11.E1(VSS1) U11.E3(VSSQ5) U11.E8(VSSQ6) U11.F1(VSSQ7) U11.G8(VSS3) U11.H1(VSSQ8) U11.H9(VSSQ9) U11.K1(VSS4) U11.K9(VSS5) U11.N1(VSS6) U11.T1(VSS7) U11.T7(VSS2) ; also on sheet 9 10 11 17 18 19 20 21 22 23 25 26 27 28 29 30 31 32 33 34 35 36 38 39 40 41 42 43 44 45 46 47 48 49 50 51 52 53 54 55 56 57 58 59 60 61 62 63 64 65 66 67 68 69 70 71 72 73 74 75 76 77
0p6V_VREF_DDR4_CH01: C99.1 C100.1 C145.1 C146.1 C191.1 U7.M1(VREFCA) U8.M1(VREFCA) U9.M1(VREFCA) U10.M1(VREFCA) U11.M1(VREFCA) ; also on sheet 9 10 11 39 72 76
0p6V_VTT_DDR4_CH01: C195.2 CN4.1 CN4.2 CN4.3 CN4.4 CN5.1 CN5.2 CN5.3 CN5.4 CN6.1 CN6.2 CN6.3 CN6.4 R65.1 R72.2 R892.1 R893.1 R894.1 R895.1 R896.1 R897.1 R898.1 R899.1 R900.1 R901.1 R902.1 R903.1 R904.1 R905.1 R906.1 R907.1 R908.1 R909.1 R910.1 R911.1 R912.1 R913.1 R914.1 R915.1 ; also on sheet 11 72
1p2V_DDR4_CH01: C107.1 C108.1 C109.1 C110.1 C111.1 C112.1 C113.1 C114.1 C115.1 C116.1 C117.1 C118.1 C119.1 C120.1 C121.1 C122.1 C123.1 C124.2 C125.2 C126.1 C127.1 C128.1 C129.1 C130.1 C131.1 C132.1 C133.1 C134.1 C135.1 C136.1 C137.1 C138.1 C139.1 C140.1 C141.1 C142.1 C143.1 C144.1 C153.1 C154.1 C155.1 C156.1 C157.1 C158.1 C159.1 C160.1 C161.1 C162.1 C163.1 C164.1 C165.1 C166.1 C167.1 C168.1 C169.1 C170.2 C171.2 C172.1 C173.1 C174.1 C175.1 C176.1 C177.1 C178.1 C179.1 C180.1 C181.1 C182.1 C183.1 C184.1 C185.1 C186.1 C187.1 C188.1 C189.1 C190.1 C7726.1 C7727.1 C7728.1 C7729.1 C7730.1 C7731.1 C7732.1 C7733.1 C7734.1 C7735.1 C7736.1 C7737.1 C7738.1 C7739.1 C7740.1 C7741.1 C7742.1 R60.1 R66.1 R67.1 R69.1 U7.A1(VDDQ0) U7.A9(VDDQ1) U7.B3(VDD0) U7.B9(VDD1) U7.C1(VDDQ2) U7.D1(VDD2) U7.D9(VDDQ3) U7.F2(VDDQ4) U7.F8(VDDQ5) U7.G1(VDDQ6) U7.G7(VDD3) U7.G9(VDDQ7) U7.J1(VDD4) U7.J2(VDDQ8) U7.J8(VDDQ9) U7.J9(VDD5) U7.L1(VDD6) U7.L9(VDD7) U7.R1(VDD8) U7.T9(VDD9) U8.A1(VDDQ0) U8.A9(VDDQ1) U8.B3(VDD0) U8.B9(VDD1) U8.C1(VDDQ2) U8.D1(VDD2) U8.D9(VDDQ3) U8.F2(VDDQ4) U8.F8(VDDQ5) U8.G1(VDDQ6) U8.G7(VDD3) U8.G9(VDDQ7) U8.J1(VDD4) U8.J2(VDDQ8) U8.J8(VDDQ9) U8.J9(VDD5) U8.L1(VDD6) U8.L9(VDD7) U8.R1(VDD8) U8.T9(VDD9) U9.A1(VDDQ0) U9.A9(VDDQ1) U9.B3(VDD0) U9.B9(VDD1) U9.C1(VDDQ2) U9.D1(VDD2) U9.D9(VDDQ3) U9.F2(VDDQ4) U9.F8(VDDQ5) U9.G1(VDDQ6) U9.G7(VDD3) U9.G9(VDDQ7) U9.J1(VDD4) U9.J2(VDDQ8) U9.J8(VDDQ9) U9.J9(VDD5) U9.L1(VDD6) U9.L9(VDD7) U9.R1(VDD8) U9.T9(VDD9) U10.A1(VDDQ0) U10.A9(VDDQ1) U10.B3(VDD0) U10.B9(VDD1) U10.C1(VDDQ2) U10.D1(VDD2) U10.D9(VDDQ3) U10.F2(VDDQ4) U10.F8(VDDQ5) U10.G1(VDDQ6) U10.G7(VDD3) U10.G9(VDDQ7) U10.J1(VDD4) U10.J2(VDDQ8) U10.J8(VDDQ9) U10.J9(VDD5) U10.L1(VDD6) U10.L9(VDD7) U10.R1(VDD8) U10.T9(VDD9) U11.A1(VDDQ0) U11.A9(VDDQ1) U11.B3(VDD0) U11.B9(VDD1) U11.C1(VDDQ2) U11.D1(VDD2) U11.D9(VDDQ3) U11.F2(VDDQ4) U11.F8(VDDQ5) U11.G1(VDDQ6) U11.G7(VDD3) U11.G9(VDDQ7) U11.J1(VDD4) U11.J2(VDDQ8) U11.J8(VDDQ9) U11.J9(VDD5) U11.L1(VDD6) U11.L9(VDD7) U11.R1(VDD8) U11.T9(VDD9) ; also on sheet 9 10 11 32 39 46 47 52 70 72 76 77
2p5V: C101.1 C102.1 C103.2 C104.1 C105.1 C106.2 C147.1 C148.1 C149.2 C150.1 C151.1 C152.2 C192.1 C193.2 C194.1 U7.B1(VPP_2V5_0) U7.R9(VPP_2V5_1) U8.B1(VPP_2V5_0) U8.R9(VPP_2V5_1) U9.B1(VPP_2V5_0) U9.R9(VPP_2V5_1) U10.B1(VPP_2V5_0) U10.R9(VPP_2V5_1) U11.B1(VPP_2V5_0) U11.R9(VPP_2V5_1) ; also on sheet 9 10 11 19 20 43 45 46 73
CLK_DDR4_CH3_N: R1067.1 U6.LW43(IO,_CLK_B_2E_1N,_DIFF_TX_2E18N,_DQ29) ; also on sheet 43
CLK_DDR4_CH3_P: R1067.2 U6.MA44(IO,_CLK_B_2E_1P,_DIFF_TX_2E18P,_DQ29) ; also on sheet 43
DDR4_COMP_CH1_A0: R892.2 U7.P3(A0) U8.P3(A0) U9.P3(A0) U10.P3(A0) U11.P3(A0) ; also on sheet 21
DDR4_COMP_CH1_A1: R893.2 U7.P7(A1) U8.P7(A1) U9.P7(A1) U10.P7(A1) U11.P7(A1) ; also on sheet 21
DDR4_COMP_CH1_A2: R894.2 U7.R3(A2) U8.R3(A2) U9.R3(A2) U10.R3(A2) U11.R3(A2) ; also on sheet 21
DDR4_COMP_CH1_A3: R895.2 U7.N7(A3) U8.N7(A3) U9.N7(A3) U10.N7(A3) U11.N7(A3) ; also on sheet 21
DDR4_COMP_CH1_A4: R896.2 U7.N3(A4) U8.N3(A4) U9.N3(A4) U10.N3(A4) U11.N3(A4) ; also on sheet 21
DDR4_COMP_CH1_A5: R897.2 U7.P8(A5) U8.P8(A5) U9.P8(A5) U10.P8(A5) U11.P8(A5) ; also on sheet 21
DDR4_COMP_CH1_A6: R898.2 U7.P2(A6) U8.P2(A6) U9.P2(A6) U10.P2(A6) U11.P2(A6) ; also on sheet 21
DDR4_COMP_CH1_A7: R899.2 U7.R8(A7) U8.R8(A7) U9.R8(A7) U10.R8(A7) U11.R8(A7) ; also on sheet 21
DDR4_COMP_CH1_A8: R900.2 U7.R2(A8) U8.R2(A8) U9.R2(A8) U10.R2(A8) U11.R2(A8) ; also on sheet 21
DDR4_COMP_CH1_A9: R901.2 U7.R7(A9) U8.R7(A9) U9.R7(A9) U10.R7(A9) U11.R7(A9) ; also on sheet 21
DDR4_COMP_CH1_A10: R902.2 U7.M3(A10_AP) U8.M3(A10_AP) U9.M3(A10_AP) U10.M3(A10_AP) U11.M3(A10_AP) ; also on sheet 21
DDR4_COMP_CH1_A11: R903.2 U7.T2(A11) U8.T2(A11) U9.T2(A11) U10.T2(A11) U11.T2(A11) ; also on sheet 21
DDR4_COMP_CH1_A12: R904.2 U7.M7(A12_BC_n) U8.M7(A12_BC_n) U9.M7(A12_BC_n) U10.M7(A12_BC_n) U11.M7(A12_BC_n) ; also on sheet 21
DDR4_COMP_CH1_A13: R905.2 U7.T8(A13) U8.T8(A13) U9.T8(A13) U10.T8(A13) U11.T8(A13) ; also on sheet 21
DDR4_COMP_CH1_A14: R906.2 U7.L2(WE_n_A14) U8.L2(WE_n_A14) U9.L2(WE_n_A14) U10.L2(WE_n_A14) U11.L2(WE_n_A14) ; also on sheet 21
DDR4_COMP_CH1_A15: R907.2 U7.M8(CAS_n_A15) U8.M8(CAS_n_A15) U9.M8(CAS_n_A15) U10.M8(CAS_n_A15) U11.M8(CAS_n_A15) ; also on sheet 21
DDR4_COMP_CH1_A16: R908.2 U7.L8(RAS_n_A16) U8.L8(RAS_n_A16) U9.L8(RAS_n_A16) U10.L8(RAS_n_A16) U11.L8(RAS_n_A16) ; also on sheet 21
DDR4_COMP_CH1_ACT_N: R915.2 U7.L3(ACT_n) U8.L3(ACT_n) U9.L3(ACT_n) U10.L3(ACT_n) U11.L3(ACT_n) ; also on sheet 21
DDR4_COMP_CH1_ALERT_N: R66.2 U7.P9(ALERT_n) U8.P9(ALERT_n) U9.P9(ALERT_n) U10.P9(ALERT_n) U11.P9(ALERT_n) ; also on sheet 21
DDR4_COMP_CH1_BA0: R911.2 U7.N2(BA0) U8.N2(BA0) U9.N2(BA0) U10.N2(BA0) U11.N2(BA0) ; also on sheet 21
DDR4_COMP_CH1_BA1: R912.2 U7.N8(BA1) U8.N8(BA1) U9.N8(BA1) U10.N8(BA1) U11.N8(BA1) ; also on sheet 21
DDR4_COMP_CH1_BG0: R909.2 U7.M2(BG0) U8.M2(BG0) U9.M2(BG0) U10.M2(BG0) U11.M2(BG0) ; also on sheet 21
DDR4_COMP_CH1_BG1: R910.2 U7.M9(BG1) U8.M9(BG1) U9.M9(BG1) U10.M9(BG1) U11.M9(BG1) ; also on sheet 21
DDR4_COMP_CH1_CKE: R70.2 R72.1 U7.K2(CKE) U8.K2(CKE) U9.K2(CKE) U10.K2(CKE) U11.K2(CKE) ; also on sheet 21
DDR4_COMP_CH1_CLK_N: R74.2 U7.K8(CK_c) U8.K8(CK_c) U9.K8(CK_c) U10.K8(CK_c) U11.K8(CK_c) ; also on sheet 21
DDR4_COMP_CH1_CLK_P: R73.2 U7.K7(CK_t) U8.K7(CK_t) U9.K7(CK_t) U10.K7(CK_t) U11.K7(CK_t) ; also on sheet 21
DDR4_COMP_CH1_CS_N: R913.2 U7.L7(CS_n) U8.L7(CS_n) U9.L7(CS_n) U10.L7(CS_n) U11.L7(CS_n) ; also on sheet 21
DDR4_COMP_CH1_DBI_N0: U11.E7(NF_LDM_n_LDBI_n) ; also on sheet 21
DDR4_COMP_CH1_DBI_N1: U8.E7(NF_LDM_n_LDBI_n) ; also on sheet 21
DDR4_COMP_CH1_DBI_N2: U7.E7(NF_LDM_n_LDBI_n) ; also on sheet 22
DDR4_COMP_CH1_DBI_N3: U8.E2(NF_UDM_n_UDBI_n) ; also on sheet 22
DDR4_COMP_CH1_DBI_N4: U9.E2(NF_UDM_n_UDBI_n) ; also on sheet 22
DDR4_COMP_CH1_DBI_N5: U10.E7(NF_LDM_n_LDBI_n) ; also on sheet 21
DDR4_COMP_CH1_DBI_N6: U9.E7(NF_LDM_n_LDBI_n) ; also on sheet 21
DDR4_COMP_CH1_DBI_N7: U7.E2(NF_UDM_n_UDBI_n) ; also on sheet 22
DDR4_COMP_CH1_DBI_N8: U10.E2(NF_UDM_n_UDBI_n) ; also on sheet 21
DDR4_COMP_CH1_DQ0: U11.H2(DQ4) ; also on sheet 21
DDR4_COMP_CH1_DQ1: U11.F7(DQ1) ; also on sheet 21
DDR4_COMP_CH1_DQ2: U11.J3(DQ6) ; also on sheet 21
DDR4_COMP_CH1_DQ3: U11.J7(DQ7) ; also on sheet 21
DDR4_COMP_CH1_DQ4: U11.H3(DQ2) ; also on sheet 21
DDR4_COMP_CH1_DQ5: U11.H8(DQ5) ; also on sheet 21
DDR4_COMP_CH1_DQ6: U11.G2(DQ0) ; also on sheet 21
DDR4_COMP_CH1_DQ7: U11.H7(DQ3) ; also on sheet 21
DDR4_COMP_CH1_DQ8: U8.J7(DQ7) ; also on sheet 21
DDR4_COMP_CH1_DQ9: U8.H3(DQ2) ; also on sheet 21
DDR4_COMP_CH1_DQ10: U8.H8(DQ5) ; also on sheet 21
DDR4_COMP_CH1_DQ11: U8.F7(DQ1) ; also on sheet 21
DDR4_COMP_CH1_DQ12: U8.G2(DQ0) ; also on sheet 21
DDR4_COMP_CH1_DQ13: U8.J3(DQ6) ; also on sheet 21
DDR4_COMP_CH1_DQ14: U8.H7(DQ3) ; also on sheet 21
DDR4_COMP_CH1_DQ15: U8.H2(DQ4) ; also on sheet 21
DDR4_COMP_CH1_DQ16: U7.F7(DQ1) ; also on sheet 22
DDR4_COMP_CH1_DQ17: U7.J7(DQ7) ; also on sheet 22
DDR4_COMP_CH1_DQ18: U7.H3(DQ2) ; also on sheet 22
DDR4_COMP_CH1_DQ19: U7.H7(DQ3) ; also on sheet 22
DDR4_COMP_CH1_DQ20: U7.H8(DQ5) ; also on sheet 22
DDR4_COMP_CH1_DQ21: U7.J3(DQ6) ; also on sheet 22
DDR4_COMP_CH1_DQ22: U7.G2(DQ0) ; also on sheet 22
DDR4_COMP_CH1_DQ23: U7.H2(DQ4) ; also on sheet 22
DDR4_COMP_CH1_DQ24: U8.B8(DQ9) ; also on sheet 22
DDR4_COMP_CH1_DQ25: U8.C3(DQ10) ; also on sheet 22
DDR4_COMP_CH1_DQ26: U8.C7(DQ11) ; also on sheet 22
DDR4_COMP_CH1_DQ27: U8.A3(DQ8) ; also on sheet 22
DDR4_COMP_CH1_DQ28: U8.D7(DQ15) ; also on sheet 22
DDR4_COMP_CH1_DQ29: U8.C2(DQ12) ; also on sheet 22
DDR4_COMP_CH1_DQ30: U8.C8(DQ13) ; also on sheet 22
DDR4_COMP_CH1_DQ31: U8.D3(DQ14) ; also on sheet 22
DDR4_COMP_CH1_DQ32: U9.C8(DQ13) ; also on sheet 22
DDR4_COMP_CH1_DQ33: U9.C2(DQ12) ; also on sheet 22
DDR4_COMP_CH1_DQ34: U9.C7(DQ11) ; also on sheet 22
DDR4_COMP_CH1_DQ35: U9.A3(DQ8) ; also on sheet 22
DDR4_COMP_CH1_DQ36: U9.D3(DQ14) ; also on sheet 22
DDR4_COMP_CH1_DQ37: U9.B8(DQ9) ; also on sheet 22
DDR4_COMP_CH1_DQ38: U9.C3(DQ10) ; also on sheet 22
DDR4_COMP_CH1_DQ39: U9.D7(DQ15) ; also on sheet 22
DDR4_COMP_CH1_DQ40: U10.H8(DQ5) ; also on sheet 21
DDR4_COMP_CH1_DQ41: U10.H3(DQ2) ; also on sheet 21
DDR4_COMP_CH1_DQ42: U10.J7(DQ7) ; also on sheet 21
DDR4_COMP_CH1_DQ43: U10.H2(DQ4) ; also on sheet 21
DDR4_COMP_CH1_DQ44: U10.H7(DQ3) ; also on sheet 21
DDR4_COMP_CH1_DQ45: U10.G2(DQ0) ; also on sheet 21
DDR4_COMP_CH1_DQ46: U10.F7(DQ1) ; also on sheet 21
DDR4_COMP_CH1_DQ47: U10.J3(DQ6) ; also on sheet 21
DDR4_COMP_CH1_DQ48: U9.J7(DQ7) ; also on sheet 21
DDR4_COMP_CH1_DQ49: U9.G2(DQ0) ; also on sheet 21
DDR4_COMP_CH1_DQ50: U9.H3(DQ2) ; also on sheet 21
DDR4_COMP_CH1_DQ51: U9.H8(DQ5) ; also on sheet 21
DDR4_COMP_CH1_DQ52: U9.J3(DQ6) ; also on sheet 21
DDR4_COMP_CH1_DQ53: U9.F7(DQ1) ; also on sheet 21
DDR4_COMP_CH1_DQ54: U9.H2(DQ4) ; also on sheet 21
DDR4_COMP_CH1_DQ55: U9.H7(DQ3) ; also on sheet 21
DDR4_COMP_CH1_DQ56: U7.D3(DQ14) ; also on sheet 22
DDR4_COMP_CH1_DQ57: U7.C3(DQ10) ; also on sheet 22
DDR4_COMP_CH1_DQ58: U7.B8(DQ9) ; also on sheet 22
DDR4_COMP_CH1_DQ59: U7.C8(DQ13) ; also on sheet 22
DDR4_COMP_CH1_DQ60: U7.C7(DQ11) ; also on sheet 22
DDR4_COMP_CH1_DQ61: U7.C2(DQ12) ; also on sheet 22
DDR4_COMP_CH1_DQ62: U7.D7(DQ15) ; also on sheet 22
DDR4_COMP_CH1_DQ63: U7.A3(DQ8) ; also on sheet 22
DDR4_COMP_CH1_DQ64: U10.B8(DQ9) ; also on sheet 21
DDR4_COMP_CH1_DQ65: U10.A3(DQ8) ; also on sheet 21
DDR4_COMP_CH1_DQ66: U10.C7(DQ11) ; also on sheet 21
DDR4_COMP_CH1_DQ67: U10.C3(DQ10) ; also on sheet 21
DDR4_COMP_CH1_DQ68: U10.D7(DQ15) ; also on sheet 21
DDR4_COMP_CH1_DQ69: U10.D3(DQ14) ; also on sheet 21
DDR4_COMP_CH1_DQ70: U10.C8(DQ13) ; also on sheet 21
DDR4_COMP_CH1_DQ71: U10.C2(DQ12) ; also on sheet 21
DDR4_COMP_CH1_DQS_N0: U11.F3(LDQS_c) ; also on sheet 21
DDR4_COMP_CH1_DQS_N1: U8.F3(LDQS_c) ; also on sheet 21
DDR4_COMP_CH1_DQS_N2: U7.F3(LDQS_c) ; also on sheet 22
DDR4_COMP_CH1_DQS_N3: U8.A7(UDQS_c) ; also on sheet 22
DDR4_COMP_CH1_DQS_N4: U9.A7(UDQS_c) ; also on sheet 22
DDR4_COMP_CH1_DQS_N5: U10.F3(LDQS_c) ; also on sheet 21
DDR4_COMP_CH1_DQS_N6: U9.F3(LDQS_c) ; also on sheet 21
DDR4_COMP_CH1_DQS_N7: U7.A7(UDQS_c) ; also on sheet 22
DDR4_COMP_CH1_DQS_N8: U10.A7(UDQS_c) ; also on sheet 21
DDR4_COMP_CH1_DQS_P0: U11.G3(LDQS_t) ; also on sheet 21
DDR4_COMP_CH1_DQS_P1: U8.G3(LDQS_t) ; also on sheet 21
DDR4_COMP_CH1_DQS_P2: U7.G3(LDQS_t) ; also on sheet 22
DDR4_COMP_CH1_DQS_P3: U8.B7(UDQS_t) ; also on sheet 22
DDR4_COMP_CH1_DQS_P4: U9.B7(UDQS_t) ; also on sheet 22
DDR4_COMP_CH1_DQS_P5: U10.G3(LDQS_t) ; also on sheet 21
DDR4_COMP_CH1_DQS_P6: U9.G3(LDQS_t) ; also on sheet 21
DDR4_COMP_CH1_DQS_P7: U7.B7(UDQS_t) ; also on sheet 22
DDR4_COMP_CH1_DQS_P8: U10.B7(UDQS_t) ; also on sheet 21
DDR4_COMP_CH1_ODT: R914.2 U7.K3(ODT) U8.K3(ODT) U9.K3(ODT) U10.K3(ODT) U11.K3(ODT) ; also on sheet 21
DDR4_COMP_CH1_PAR: R65.2 U7.T3(PAR) U8.T3(PAR) U9.T3(PAR) U10.T3(PAR) U11.T3(PAR) ; also on sheet 21
DDR4_COMP_CH1_RESET_N: R67.2 R68.2 U7.P1(RESET_n) U8.P1(RESET_n) U9.P1(RESET_n) U10.P1(RESET_n) U11.P1(RESET_n) ; also on sheet 21
DDR4_COMP_CH1_TEN: R69.2 R71.1 U7.N9(TEN_VSS) U8.N9(TEN_VSS) U9.N9(TEN_VSS) U10.N9(TEN_VSS) U11.N9(TEN_VSS)
DDR4_DDIMM2_A0: U6.KR45(IO,_DIFF_TX_2E21P,_DQ30) ; also on sheet 19
DDR4_DDIMM2_A1: U6.KU44(IO,_DIFF_TX_2E21N,_DQ30) ; also on sheet 19
DDR4_DDIMM2_A2: U6.KJ45(IO,_CDR,_DIFF_RX_2E21P,_DQ30) ; also on sheet 19
DDR4_DDIMM2_A3: U6.KF44(IO,_CDR,_DIFF_RX_2E21N,_DQ30) ; also on sheet 19
DDR4_DDIMM2_A4: U6.KU46(IO,_DIFF_TX_2E20P,_DQS30) ; also on sheet 19
DDR4_DDIMM2_A5: U6.KR47(IO,_DIFF_TX_2E20N,_DQSN30) ; also on sheet 19
DDR4_DDIMM2_A6: U6.KF46(IO,_PLL_2E_B_CLKOUT0P,_PLL_2E_B_CLKOUT0,_PLL_2E_B_FB0,_DIFF_RX_2E20P,_DQ30) ; also on sheet 19
DDR4_DDIMM2_A7: U6.KJ47(IO,_PLL_2E_B_CLKOUT0N,_DIFF_RX_2E20N,_DQ30) ; also on sheet 19
DDR4_DDIMM2_A8: U6.KR49(IO,_DIFF_TX_2E19P,_DQ30) ; also on sheet 19
DDR4_DDIMM2_A9: U6.KU48(IO,_DIFF_TX_2E19N,_DQ30) ; also on sheet 19
DDR4_DDIMM2_A10: U6.KF48(IO,_CLK_B_2E_0P,_CDR,_DIFF_RX_2E19P,_DQ30) ; also on sheet 19
DDR4_DDIMM2_A11: U6.KJ49(IO,_CLK_B_2E_0N,_CDR,_DIFF_RX_2E19N,_DQ30) ; also on sheet 19
DDR4_DDIMM2_A12: U6.LR43(IO,_CDR,_DIFF_RX_2E18N,_DQ29) ; also on sheet 19
DDR4_DDIMM2_A13: U6.LW45(IO,_PLL_2E_B_CLKOUT1P,_PLL_2E_B_CLKOUT1,_PLL_2E_B_FB1,_DIFF_TX_2E17P,_DQS29) ; also on sheet 19
DDR4_DDIMM2_A14: U6.MA46(IO,_PLL_2E_B_CLKOUT1N,_DIFF_TX_2E17N,_DQSN29) ; also on sheet 19
DDR4_DDIMM2_A15: U6.LR45(IO,_DIFF_RX_2E17P,_DQ29) ; also on sheet 19
DDR4_DDIMM2_A16: U6.LN46(IO,_DIFF_RX_2E17N,_DQ29) ; also on sheet 19
DDR4_DDIMM2_A17: U6.MA48(IO,_DIFF_TX_2E16P,_DQ29) ; also on sheet 19
DDR4_DDIMM2_ACT_N: U6.KW45(IO,_CDR,_DIFF_RX_2E24N,_DQ31) ; also on sheet 19
DDR4_DDIMM2_ALERT_N: U6.MA54(IO,_DIFF_TX_2E13P,_DQ28) ; also on sheet 19
DDR4_DDIMM2_BA0: U6.LW47(IO,_DIFF_TX_2E16N,_DQ29) ; also on sheet 19
DDR4_DDIMM2_BA1: U6.LN48(IO,_CDR,_DIFF_RX_2E16P,_DQ29) ; also on sheet 19
DDR4_DDIMM2_BG0: U6.LR47(IO,_CDR,_DIFF_RX_2E16N,_DQ29) ; also on sheet 19
DDR4_DDIMM2_BG1: U6.LH44(IO,_DIFF_TX_2E24P,_DQ31) ; also on sheet 19
DDR4_DDIMM2_C0: R1074.1 U6.MA50(IO,_DIFF_TX_2E15P,_DQ28)
DDR4_DDIMM2_C0_CS_N2: R1074.2 R1075.2 ; also on sheet 19
DDR4_DDIMM2_C1: R1076.1 U6.LW49(IO,_DIFF_TX_2E15N,_DQ28)
DDR4_DDIMM2_C1_CS_N3: R1076.2 R1077.2 ; also on sheet 19
DDR4_DDIMM2_CS_N2: R1075.1 U6.LR51(IO,_DIFF_RX_2E14P,_DQ28)
DDR4_DDIMM2_CS_N3: R1077.1 U6.LN52(IO,_DIFF_RX_2E14N,_DQ28)
DDR4_DDIMM2_DBI_N1: U6.LR39(IO,_PLL_2E_T_CLKOUT0P,_PLL_2E_T_CLKOUT0,_PLL_2E_T_FB0,_DIFF_RX_2E8P,_DQ26) ; also on sheet 19
DDR4_DDIMM2_DBI_N3: U6.MD36(IO,_DIFF_RX_2E11P,_DQ27) ; also on sheet 19
DDR4_DDIMM2_DBI_N4: U6.MD48(IO,_DIFF_RX_2E2P,_DQ24) ; also on sheet 19
DDR4_DDIMM2_DBI_N8: U6.MD42(IO,_DIFF_RX_2E5P,_DQ25) ; also on sheet 19
DDR4_DDIMM2_DQ8: U6.LW37(IO,_DIFF_TX_2E9P,_DQ26) ; also on sheet 19
DDR4_DDIMM2_DQ9: U6.LR37(IO,_CDR,_DIFF_RX_2E9N,_DQ26) ; also on sheet 19
DDR4_DDIMM2_DQ10: U6.MA38(IO,_DIFF_TX_2E9N,_DQ26) ; also on sheet 19
DDR4_DDIMM2_DQ11: U6.LN38(IO,_CDR,_DIFF_RX_2E9P,_DQ26) ; also on sheet 19
DDR4_DDIMM2_DQ12: U6.MA42(IO,_DIFF_TX_2E7P,_DQ26) ; also on sheet 19
DDR4_DDIMM2_DQ13: U6.LW41(IO,_DIFF_TX_2E7N,_DQ26) ; also on sheet 19
DDR4_DDIMM2_DQ14: U6.LN42(IO,_CLK_T_2E_0P,_DIFF_RX_2E7P,_DQ26) ; also on sheet 19
DDR4_DDIMM2_DQ15: U6.LR41(IO,_CLK_T_2E_0N,_DIFF_RX_2E7N,_DQ26) ; also on sheet 19
DDR4_DDIMM2_DQ24: U6.MK35(IO,_DIFF_TX_2E12P,_DQ27) ; also on sheet 19
DDR4_DDIMM2_DQ25: U6.MC35(IO,_CDR,_DIFF_RX_2E12P,_DQ27) ; also on sheet 19
DDR4_DDIMM2_DQ26: U6.MD34(IO,_CDR,_DIFF_RX_2E12N,_DQ27) ; also on sheet 19
DDR4_DDIMM2_DQ27: U6.MH34(IO,_DIFF_TX_2E12N,_DQ27) ; also on sheet 19
DDR4_DDIMM2_DQ28: U6.MK39(IO,_DIFF_TX_2E10P,_DQ27) ; also on sheet 19
DDR4_DDIMM2_DQ29: U6.MC39(IO,_DIFF_RX_2E10N,_DQ27) ; also on sheet 19
DDR4_DDIMM2_DQ30: U6.MD38(IO,_DIFF_RX_2E10P,_DQ27) ; also on sheet 19
DDR4_DDIMM2_DQ31: U6.MH38(IO,_DIFF_TX_2E10N,_DQ27) ; also on sheet 19
DDR4_DDIMM2_DQ32: U6.MC47(IO,_CDR,_DIFF_RX_2E3P,_DQ24) ; also on sheet 19
DDR4_DDIMM2_DQ33: U6.MK47(IO,_DIFF_TX_2E3P,_DQ24) ; also on sheet 19
DDR4_DDIMM2_DQ34: U6.MH46(IO,_DIFF_TX_2E3N,_DQ24) ; also on sheet 19
DDR4_DDIMM2_DQ35: U6.MD46(IO,_CDR,_DIFF_RX_2E3N,_DQ24) ; also on sheet 19
DDR4_DDIMM2_DQ36: U6.MC51(IO,_DIFF_RX_2E1N,_DQ24) ; also on sheet 19
DDR4_DDIMM2_DQ37: U6.MK51(IO,_DIFF_TX_2E1P,_DQ24) ; also on sheet 19
DDR4_DDIMM2_DQ38: U6.MD50(IO,_DIFF_RX_2E1P,_DQ24) ; also on sheet 19
DDR4_DDIMM2_DQ39: U6.MH50(IO,_DIFF_TX_2E1N,_DQ24) ; also on sheet 19
DDR4_DDIMM2_DQ64: U6.MH40(IO,_CLK_T_2E_1N,_DIFF_TX_2E6N,_DQ25) ; also on sheet 19
DDR4_DDIMM2_DQ65: U6.MD40(IO,_CDR,_DIFF_RX_2E6N,_DQ25) ; also on sheet 19
DDR4_DDIMM2_DQ66: U6.MC41(IO,_RZQ_T_2E,_CDR,_DIFF_RX_2E6P,_DQ25) ; also on sheet 19
DDR4_DDIMM2_DQ67: U6.MK41(IO,_CLK_T_2E_1P,_DIFF_TX_2E6P,_DQ25) ; also on sheet 19
DDR4_DDIMM2_DQ68: U6.MH44(IO,_DIFF_TX_2E4N,_DQ25) ; also on sheet 19
DDR4_DDIMM2_DQ69: U6.MK45(IO,_DIFF_TX_2E4P,_DQ25) ; also on sheet 19
DDR4_DDIMM2_DQ70: U6.MD44(IO,_DIFF_RX_2E4N,_DQ25) ; also on sheet 19
DDR4_DDIMM2_DQ71: U6.MC45(IO,_DIFF_RX_2E4P,_DQ25) ; also on sheet 19
DDR4_DDIMM2_DQS_N1: U6.MA40(IO,_DIFF_TX_2E8N,_DQSN26) ; also on sheet 19
DDR4_DDIMM2_DQS_N3: U6.MK37(IO,_DIFF_TX_2E11N,_DQSN27) ; also on sheet 19
DDR4_DDIMM2_DQS_N4: U6.MK49(IO,_DIFF_TX_2E2N,_DQSN24) ; also on sheet 19
DDR4_DDIMM2_DQS_N8: U6.MK43(IO,_PLL_2E_T_CLKOUT1N,_DIFF_TX_2E5N,_DQSN25) ; also on sheet 19
DDR4_DDIMM2_DQS_P1: U6.LW39(IO,_DIFF_TX_2E8P,_DQS26) ; also on sheet 19
DDR4_DDIMM2_DQS_P3: U6.MH36(IO,_DIFF_TX_2E11P,_DQS27) ; also on sheet 19
DDR4_DDIMM2_DQS_P4: U6.MH48(IO,_DIFF_TX_2E2P,_DQS24) ; also on sheet 19
DDR4_DDIMM2_DQS_P8: U6.MH42(IO,_PLL_2E_T_CLKOUT1P,_PLL_2E_T_CLKOUT1,_PLL_2E_T_FB1,_DIFF_TX_2E5P,_DQS25) ; also on sheet 19
DDR4_DDIMM2_PAR: U6.LB48(IO,_CDR,_DIFF_RX_2E22N,_DQ31) ; also on sheet 19
DDR4_DDIMM2_RESET_N: U6.LL45(IO,_DIFF_TX_2E24N,_DQ31) ; also on sheet 19
DDR4_DDIMM2_RZQ: R37.1 U6.LN44(IO,_RZQ_B_2E,_CDR,_DIFF_RX_2E18P,_DQ29)
DDR4_DDIMM2_TDQS_N10: U6.LN40(IO,_PLL_2E_T_CLKOUT0N,_DIFF_RX_2E8N,_DQ26) ; also on sheet 19
DDR4_DDIMM2_TDQS_N12: U6.MC37(IO,_DIFF_RX_2E11N,_DQ27) ; also on sheet 19
DDR4_DDIMM2_TDQS_N13: U6.MC49(IO,_DIFF_RX_2E2N,_DQ24) ; also on sheet 19
DDR4_DDIMM2_TDQS_N17: U6.MC43(IO,_DIFF_RX_2E5N,_DQ25) ; also on sheet 19
DDR4_DIMM2_CK_N0: U6.LL49(IO,_DIFF_TX_2E22N,_DQ31) ; also on sheet 19
DDR4_DIMM2_CK_N1: U6.LN54(IO,_CDR,_DIFF_RX_2E13N,_DQ28) ; also on sheet 19
DDR4_DIMM2_CK_P0: U6.LH48(IO,_DIFF_TX_2E22P,_DQ31) ; also on sheet 19
DDR4_DIMM2_CK_P1: U6.LR53(IO,_CDR,_DIFF_RX_2E13P,_DQ28) ; also on sheet 19
DDR4_DIMM2_CKE0: U6.LB46(IO,_DIFF_RX_2E23P,_DQ31) ; also on sheet 19
DDR4_DIMM2_CKE1: U6.KW47(IO,_DIFF_RX_2E23N,_DQ31) ; also on sheet 19
DDR4_DIMM2_CS_N0: U6.LB44(IO,_CDR,_DIFF_RX_2E24P,_DQ31) ; also on sheet 19
DDR4_DIMM2_CS_N1: U6.KW49(IO,_CDR,_DIFF_RX_2E22P,_DQ31) ; also on sheet 19
DDR4_DIMM2_ODT0: U6.LH46(IO,_DIFF_TX_2E23P,_DQS31) ; also on sheet 19
DDR4_DIMM2_ODT1: U6.LL47(IO,_DIFF_TX_2E23N,_DQSN31) ; also on sheet 19
N23628441: C196.1 R73.1 R74.1
N30729048: R62.1 U11.F9(ZQ0)
N30732060: R51.2 U11.A3(DQ8)
N30732063: R52.2 U11.B8(DQ9)
N30732066: R53.2 U11.C3(DQ10)
N30732069: R54.2 U11.C7(DQ11)
N30732072: R55.2 U11.C2(DQ12)
N30732075: R56.2 U11.C8(DQ13)
N30732078: R57.2 U11.D3(DQ14)
N30732081: R58.2 U11.D7(DQ15)
N30732436: R59.2 U11.E2(NF_UDM_n_UDBI_n)
N30732839: R60.2 U11.B7(UDQS_t)
N30732842: R61.2 U11.A7(UDQS_c)
N31559457: R63.1 U11.E9(ZQ1)
N39073276: R39.1 U7.F9(ZQ0)
N39073371: R40.1 U8.F9(ZQ0)
N39073461: R41.1 U7.E9(ZQ1)
N39073464: R42.1 U8.E9(ZQ1)
N39075525: R45.1 U9.F9(ZQ0)
N39075684: R46.1 U10.F9(ZQ0)
N39075769: R47.1 U9.E9(ZQ1)
N39075772: R48.1 U10.E9(ZQ1)

Not connected (* = marked no-connect by the designer): U6 LN50(IO,_CDR,_DIFF_RX_2E15P,_DQ28)* LR49(IO,_CDR,_DIFF_RX_2E15N,_DQ28)* LW51(IO,_DIFF_TX_2E14P,_DQS28)* LW53(IO,_DIFF_TX_2E13N,_DQ28)* MA52(IO,_DIFF_TX_2E14N,_DQSN28)*

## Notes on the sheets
sheet 13
- DDR4/T DIMM CH1  INTERFACE -- FPGA SIDE 2E
sheet 14
- DDR4 COMPONENT #1/#2
- CAD Note: the footprint should be compatible
  with 16Gb part MT40A1G16KNR
sheet 15
- DDR4 COMPONENT #3/#4
sheet 16
- DDR4 COMPONENT #5 & Termination
